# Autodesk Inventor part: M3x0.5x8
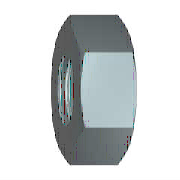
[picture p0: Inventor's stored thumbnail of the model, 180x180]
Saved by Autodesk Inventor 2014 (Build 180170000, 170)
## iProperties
Created: 2009-02
Part Number: M3x0.5x8
Material: 강, 연강
Description: 6각 너트 및 6각 가는 너트
Document SubType Name: Modeling
Standard: KS B 1012
Designer: KYOUNG IL JANG
Standards Organization: KS
Language: ko-KR
Size Designation: C M8
Categories: <MemberInstance><Categories><Category DisplayName="조임쇠" InternalName="e4da775c-781d-43d5-af7c-5136215cf5a6" Mnemonic="FSTN"><Category DisplayName="너트" InternalN
Density: 7.86 g/cm^3
Vendor: CBT Solutions
Appearance: 강철
Mass: 6.84944 g
Surface Area: 7.1883 cm^2
Volume: 0.87143 cm^3
Company: 한국ATC센터
IsCustomPart: 0
Author: KYOUNG IL JANG
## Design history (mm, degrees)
sketch "스케치1"
  geometry: L1 (-7.506, 0)-(-3.753, 6.5); L2 (-3.753, 6.5)-(3.753, 6.5); L3 (3.753, 6.5)-(7.506, 0); L4 (7.506, 0)-(3.753, -6.5); L5 (3.753, -6.5)-(-3.753, -6.5); L6 (-3.753, -6.5)-(-7.506, 0); 2 further points
  constraints: 12 end point, 1 coincident, 1 horizontal, 11 other
  dimensions: "d0" = 15.01111 distance of L3.end L1.start (= 1.1547 x SW)
extrude "본체" new body sketch "스케치1" distance "d1" = 7.9 (= KOH); taper "d2" = 0 deg
sketch "스케치2"
  geometry: L1 (0, 3.753)-(0, 7.506) reference; L2 (0, 7.506)-(7.9, 7.506) reference; L3 (7.9, 3.753)-(7.9, 7.506) reference; L4 (-1.58, 0)-(9.48, 0) reference; L5 (0.581, 7.506)-(0, 6.5); L6 (7.319, 7.506)-(7.9, 6.5)
  constraints: 4 end point, 4 point on line
  dimensions: "d3" = 30 deg angle of L1 L5 (= ANG1); "d4" = 30 deg angle of L3 L6 (= ANG2); "d5" = 13 diameter of L5.end L4 (= SW0); "d6" = 13 diameter of L6.end L4 (= SW01)
revolve "모따기1" sketch "스케치2" stored, may be unused: angle "d7" = 90 deg
sketch "스케치3"
  geometry: A1 r 6.5 centre (0, 0) between (-3.25, -5.629) and (3.25, -5.629) reference; 1 further point
  constraints: 1 coincident
hole "스레드" sketch "스케치3" at (0, 0) diameter "d25" = 6.647; stored, may be unused: countersink angle "d29" = 82 deg, drill point angle "d31" = 118 deg; dims "d26" = 6, "d27" = 4, "d28" = 2, "d30" = 8
workaxis "Work Axis1"
workplane "Work Plane1"
body "Solid1"
chamfer "모따기2" distance "d8" = 0.67658 (= -0.5 x GD1 + 0.5 x NND); stored, may be unused: angle "d9" = 30 deg, second distance "d40" = 0.67658 (= -0.5 x GD1 + 0.5 x NND)
chamfer "모따기3" distance "d10" = 0.67658 (= -0.5 x GD1 + 0.5 x NND); stored, may be unused: angle "d11" = 30 deg, second distance "d41" = 0.67658 (= -0.5 x GD1 + 0.5 x NND)
other parameters: "ANG1" = 30 deg [user parameter; used in 1 equation term], "ANG2" = 30 deg [user parameter; used in 1 equation term], "NND" = 8 [user parameter; used in 4 equation terms], "KOH" = 7.9 [user parameter; used in 1 equation term], "SW" = 13 [user parameter; used in 4 equation terms], "SW0" = 13 (= SW) [user parameter; used in 1 equation term], "SW01" = 13 (= SW) [user parameter; used in 1 equation term], "GD1" = 6.64684 (computed from THREADDIA, PTC, TOA) [user parameter; used in 4 equation terms], "d13" = 0, "d14" = 0, "d39" = 0, "d42" = 0, "GUL" = 0.67658 (= 0.541266 x PTC) [user parameter], "TPU" = 8 (computed from PTC) [user parameter], "THREADDIA" = 8 [user parameter; used in 1 equation term], "TOA" = 30 deg [user parameter; used in 1 equation term], "PTC" = 1.25 [user parameter; used in 4 equation terms], "E0" = 15.015 (= 1.155 x SW) [user parameter], "GAL" = 0.67658 (= 0.541266 x PTC) [user parameter]
